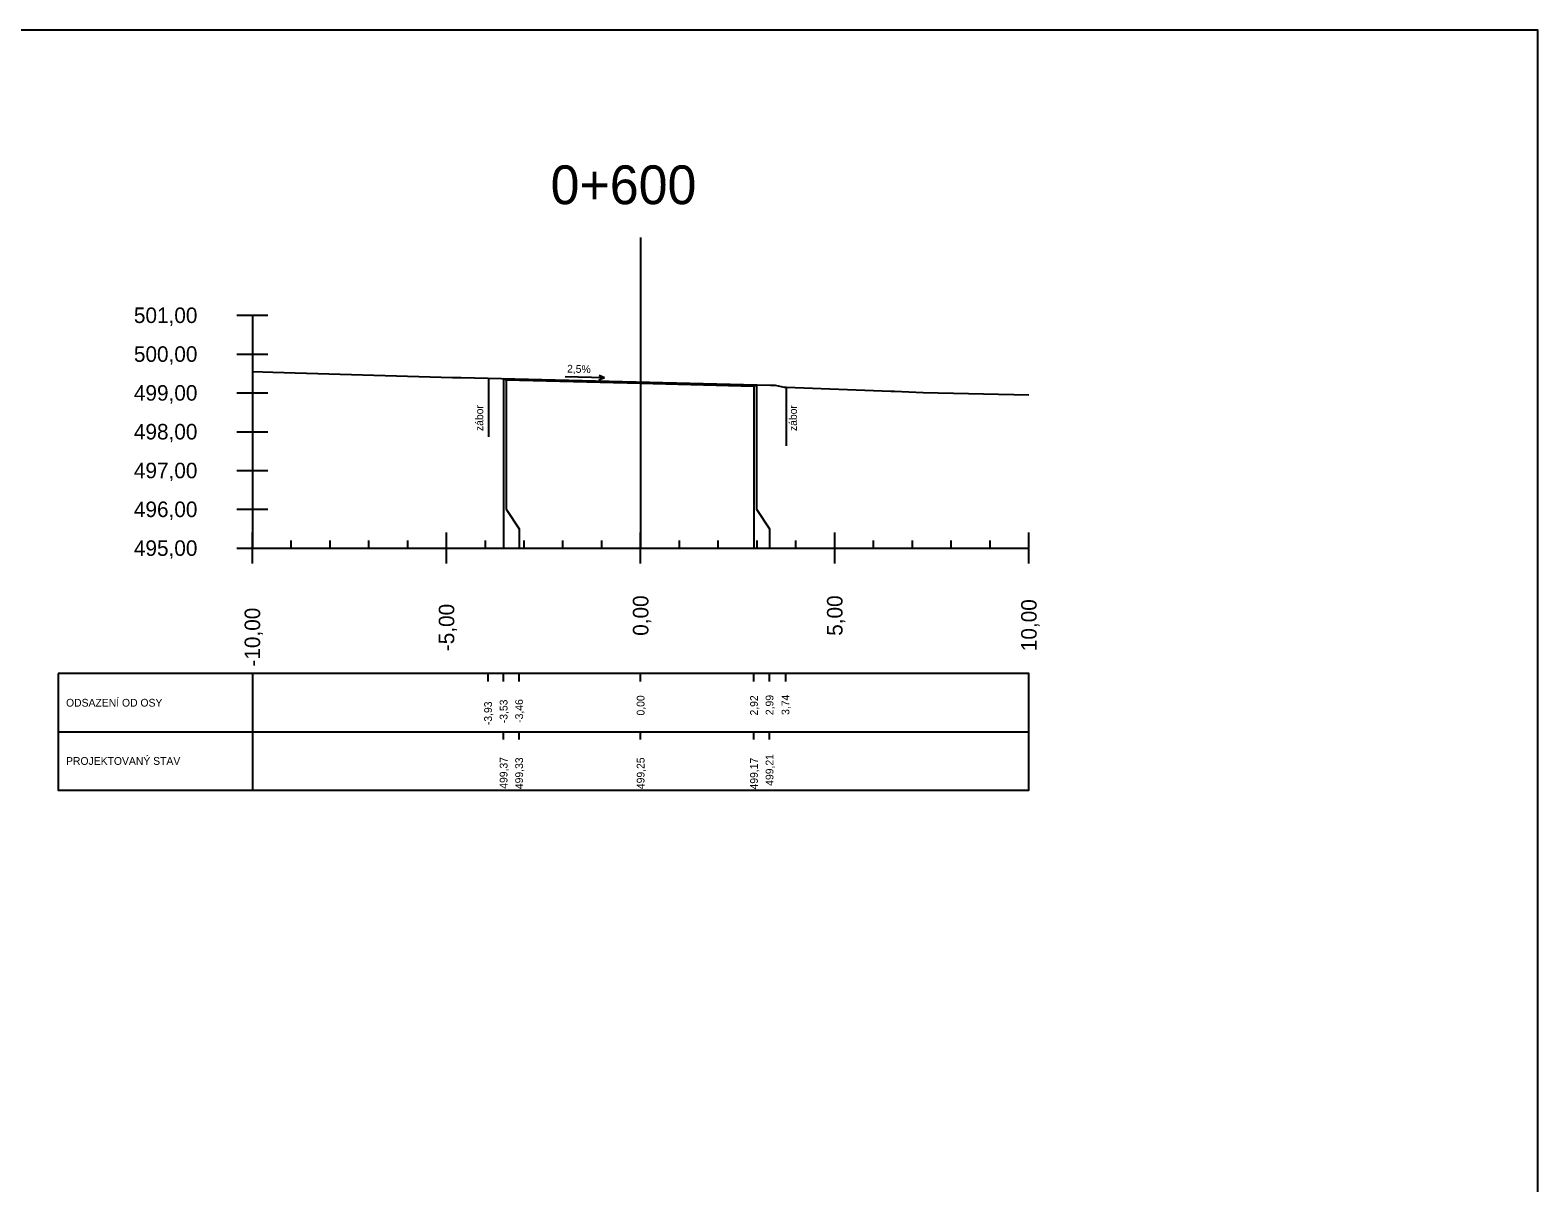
# Model space of a CAD drawing. Extents: x -631407 to -631215, y -1089700 to -1088598.
# Drawn here: x -631281.67 to -631242.84, y -1088627.41 to -1088597.71 of the extents above; entities that cross this region are included whole.
import ezdxf

# ---------------------------------------------------------------- set-up
doc = ezdxf.new("R2010")
doc.units = 0
for name, color, linetype in [('08_LEGENDA_HV', 7, 'Continuous'), ('59', 7, 'Continuous'), ('NIVELETA_VYSKY', 7, 'Continuous'), ('REZ_BODY', 7, 'Continuous'), ('REZ_ODSTUPY', 7, 'Continuous'), ('REZ_POPIS', 7, 'Continuous'), ('REZ_RAMY', 7, 'Continuous'), ('REZ_STANICENI', 7, 'Continuous'), ('REZ_SVISLE', 7, 'Continuous'), ('REZ_TENKA', 7, 'Continuous'), ('REZ_TLUSTA', 7, 'Continuous'), ('TABULKA_POPIS', 7, 'Continuous'), ('TEREN', 7, 'Continuous'), ('zábor', 7, 'Continuous')]:
    doc.layers.add(name, color=color, linetype=linetype)

msp = doc.modelspace()

# ---------------------------------------------------------------- linework, layer by layer
at = {"layer": '08_LEGENDA_HV'}
msp.add_lwpolyline([(-631242.839, -1088657.106), (-631242.839, -1088597.706), (-631407.014, -1088597.706), (-631407.014, -1088657.106)], close=True, dxfattribs=at)
at = {"layer": '59'}
for p, q in [((-631276.349, -1088605.052), (-631275.549, -1088605.052)), ((-631275.949, -1088605.052), (-631275.949, -1088611.052)), ((-631276.349, -1088606.052), (-631275.549, -1088606.052)), ((-631276.349, -1088607.052), (-631275.549, -1088607.052)), ((-631276.349, -1088608.052), (-631275.549, -1088608.052)), ((-631276.349, -1088609.052), (-631275.549, -1088609.052)), ((-631276.349, -1088610.052), (-631275.549, -1088610.052)), ((-631276.349, -1088611.052), (-631275.549, -1088611.052))]:
    msp.add_line(p, q, dxfattribs=at)
at = {"layer": 'REZ_RAMY'}
for p, q in [((-631280.949, -1088614.286), (-631280.949, -1088617.286)), ((-631275.949, -1088614.286), (-631275.949, -1088617.286)), ((-631269.879, -1088614.486), (-631269.879, -1088614.286)), ((-631269.478, -1088614.486), (-631269.478, -1088614.286)), ((-631269.079, -1088614.486), (-631269.079, -1088614.286)), ((-631265.949, -1088614.486), (-631265.949, -1088614.286)), ((-631263.029, -1088614.486), (-631263.029, -1088614.286)), ((-631262.629, -1088614.486), (-631262.629, -1088614.286)), ((-631262.209, -1088614.486), (-631262.209, -1088614.286)), ((-631280.949, -1088615.786), (-631255.949, -1088615.786)), ((-631269.478, -1088615.986), (-631269.478, -1088615.786)), ((-631269.079, -1088615.986), (-631269.079, -1088615.786)), ((-631265.949, -1088615.986), (-631265.949, -1088615.786)), ((-631263.029, -1088615.986), (-631263.029, -1088615.786)), ((-631262.629, -1088615.986), (-631262.629, -1088615.786))]:
    msp.add_line(p, q, dxfattribs=at)
msp.add_lwpolyline([(-631280.949, -1088614.286), (-631280.949, -1088617.286), (-631255.949, -1088617.286), (-631255.949, -1088614.286)], close=True, dxfattribs=at)
at = {"layer": 'REZ_SVISLE'}
for points in [[(-631269.478, -1088606.685), (-631269.478, -1088610.052), (-631269.478, -1088610.552), (-631269.478, -1088611.052)], [(-631269.409, -1088606.72), (-631269.409, -1088610.052), (-631269.079, -1088610.552), (-631269.079, -1088611.052)], [(-631265.949, -1088606.806), (-631265.949, -1088610.052), (-631265.949, -1088610.552), (-631265.949, -1088611.052)], [(-631263.029, -1088606.879), (-631263.029, -1088610.052), (-631263.029, -1088610.552), (-631263.029, -1088611.052)], [(-631262.962, -1088606.846), (-631262.962, -1088610.052), (-631262.629, -1088610.552), (-631262.629, -1088611.052)]]:
    msp.add_lwpolyline(points, dxfattribs=at)
at = {"layer": 'REZ_TENKA'}
for p, q in [((-631274.949, -1088611.052), (-631274.949, -1088610.852)), ((-631273.949, -1088611.052), (-631273.949, -1088610.852)), ((-631272.949, -1088611.052), (-631272.949, -1088610.852)), ((-631271.949, -1088611.052), (-631271.949, -1088610.852)), ((-631269.949, -1088611.052), (-631269.949, -1088610.852)), ((-631268.949, -1088611.052), (-631268.949, -1088610.852)), ((-631267.949, -1088611.052), (-631267.949, -1088610.852)), ((-631266.949, -1088611.052), (-631266.949, -1088610.852)), ((-631264.949, -1088611.052), (-631264.949, -1088610.852)), ((-631263.949, -1088611.052), (-631263.949, -1088610.852)), ((-631262.949, -1088611.052), (-631262.949, -1088610.852)), ((-631261.949, -1088611.052), (-631261.949, -1088610.852)), ((-631259.949, -1088611.052), (-631259.949, -1088610.852)), ((-631258.949, -1088611.052), (-631258.949, -1088610.852)), ((-631257.949, -1088611.052), (-631257.949, -1088610.852)), ((-631256.949, -1088611.052), (-631256.949, -1088610.852))]:
    msp.add_line(p, q, dxfattribs=at)
at = {"layer": 'REZ_TLUSTA'}
for p, q in [((-631265.949, -1088603.052), (-631265.949, -1088611.052)), ((-631275.949, -1088611.452), (-631275.949, -1088610.652)), ((-631270.949, -1088611.452), (-631270.949, -1088610.652)), ((-631265.949, -1088611.452), (-631265.949, -1088610.652)), ((-631260.949, -1088611.452), (-631260.949, -1088610.652)), ((-631255.949, -1088611.452), (-631255.949, -1088610.652)), ((-631275.949, -1088611.052), (-631255.949, -1088611.052))]:
    msp.add_line(p, q, dxfattribs=at)
at = {"layer": 'TEREN'}
for points in [[(-631275.949, -1088606.5), (-631275.424, -1088606.515), (-631270.791, -1088606.653), (-631270.57, -1088606.658), (-631262.601, -1088606.855), (-631262.483, -1088606.853), (-631262.248, -1088606.905), (-631262.232, -1088606.906), (-631262.193, -1088606.909), (-631259.508, -1088607.005), (-631259.463, -1088607.007), (-631259.414, -1088607.006), (-631258.673, -1088607.039), (-631255.949, -1088607.104)], [(-631269.478, -1088606.685), (-631269.409, -1088606.72), (-631265.949, -1088606.806), (-631263.029, -1088606.879), (-631262.962, -1088606.846)]]:
    msp.add_lwpolyline(points, dxfattribs=at)
at = {"layer": 'zábor'}
for p, q in [((-631269.865, -1088606.676), (-631269.865, -1088608.182)), ((-631266.882, -1088606.666), (-631267.89, -1088606.64)), ((-631266.882, -1088606.666), (-631267.022, -1088606.723)), ((-631266.882, -1088606.666), (-631267.019, -1088606.601)), ((-631262.201, -1088606.908), (-631262.201, -1088608.419))]:
    msp.add_line(p, q, dxfattribs=at)

# ---------------------------------------------------------------- texts
at = {"layer": 'NIVELETA_VYSKY'}
for s, p in [('499,21', (-631262.529, -1088617.176)), ('499,37', (-631269.378, -1088617.252)), ('499,33', (-631268.979, -1088617.262)), ('499,25', (-631265.849, -1088617.262)), ('499,17', (-631262.929, -1088617.271))]:
    msp.add_text(s, height=0.2, rotation=90, dxfattribs=at).set_placement(p)
at = {"layer": 'REZ_BODY'}
for s, p in [('0,00', (-631265.849, -1088615.365)), ('2,92', (-631262.929, -1088615.365)), ('2,99', (-631262.529, -1088615.355)), ('3,74', (-631262.118, -1088615.349)), ('-3,93', (-631269.779, -1088615.613)), ('-3,53', (-631269.378, -1088615.563)), ('-3,46', (-631268.979, -1088615.554))]:
    msp.add_text(s, height=0.2, rotation=90, dxfattribs=at).set_placement(p)
at = {"layer": 'REZ_ODSTUPY'}
for s, p in [('-5,00', (-631270.749, -1088613.707)), ('0,00', (-631265.749, -1088613.311)), ('5,00', (-631260.749, -1088613.311)), ('10,00', (-631255.749, -1088613.707)), ('-10,00', (-631275.749, -1088614.104))]:
    msp.add_text(s, height=0.4, rotation=90, dxfattribs=at).set_placement(p)
at = {"layer": 'REZ_POPIS'}
for s, p in [('501,00', (-631279.001, -1088605.252)), ('500,00', (-631279.001, -1088606.252)), ('499,00', (-631279.001, -1088607.252)), ('498,00', (-631279.001, -1088608.252)), ('497,00', (-631279.001, -1088609.252)), ('496,00', (-631279.001, -1088610.252)), ('495,00', (-631279.001, -1088611.252))]:
    msp.add_text(s, height=0.4, dxfattribs=at).set_placement(p)
at = {"layer": 'REZ_STANICENI'}
msp.add_text('0+600', height=1, dxfattribs=at).set_placement((-631268.268, -1088602.191))
at = {"layer": 'TABULKA_POPIS'}
for s, p in [('ODSAZENÍ OD OSY', (-631280.749, -1088615.136)), ('PROJEKTOVANÝ STAV', (-631280.749, -1088616.636))]:
    msp.add_text(s, height=0.2, dxfattribs=at).set_placement(p)
at = {"layer": 'zábor'}
for s, rotation, p in [('2,5%', 358.5679, (-631267.846, -1088606.528)), ('zábor', 90, (-631270.004, -1088608.036)), ('zábor', 90, (-631261.924, -1088608.036))]:
    msp.add_text(s, height=0.2, rotation=rotation, dxfattribs=at).set_placement(p)

doc.saveas('drawing.dxf')
